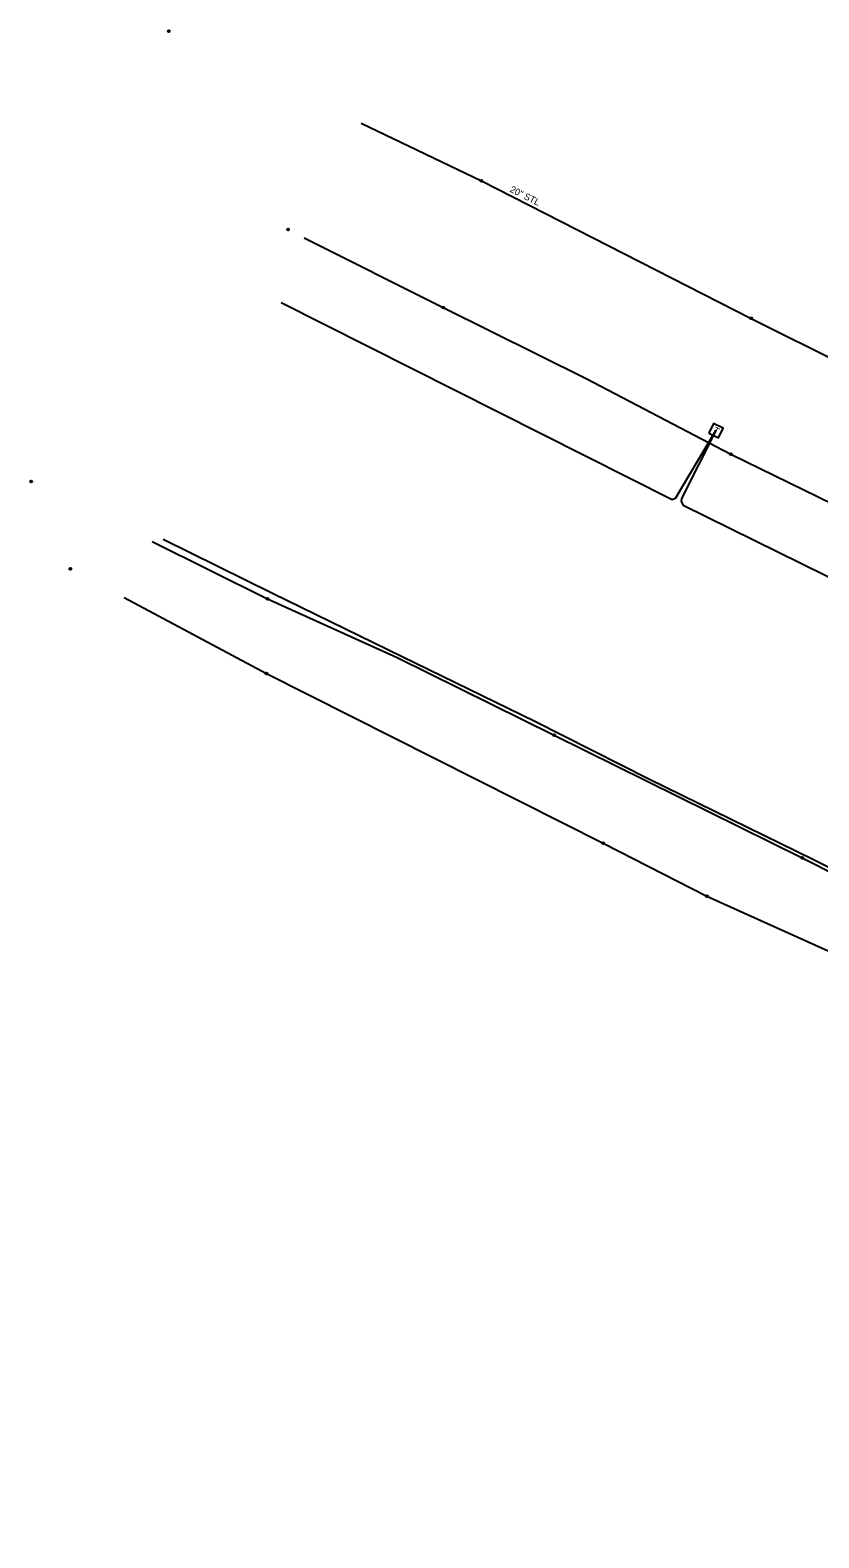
# Model space of a CAD drawing. Extents: x 2244485 to 2250986, y 199568 to 203007.
# Drawn here: x 2244485 to 2244899, y 202217 to 203007 of the extents above; entities that cross this region are included whole.
import ezdxf

# ---------------------------------------------------------------- set-up
doc = ezdxf.new("R2010")
doc.units = 0
for name, color, linetype in [('Default', 7, 'Continuous'), ('Exist Utilities Gas UG Line SUE LOS B', 7, 'Continuous'), ('Exist Utilities Gas UG Line SUE LOS B Text', 7, 'Continuous'), ('Exist Utilities Telephone Pedestal CELL', 7, 'Continuous'), ('Exist Utilities Telephone UG Cable SUE LOS C', 7, 'Continuous'), ('Exist Utilities Telephone UG FO SUE LOS B', 7, 'Continuous'), ('Exist Utilities Telephone UG FO SUE LOS C', 7, 'Continuous')]:
    doc.layers.add(name, color=color, linetype=linetype)

# ---------------------------------------------------------------- blocks, each defined once
blk = doc.blocks.new('SurveyPointCell')
at = {"layer": 'Default'}
for p, q in [((-0.5, 0), (0.5, 0)), ((0, -0.5), (0, 0.5))]:
    blk.add_line(p, q, dxfattribs=at)
blk.add_circle((0, 0), 0.5, dxfattribs=at)

msp = doc.modelspace()

# ---------------------------------------------------------------- linework, layer by layer
at = {"layer": 'Exist Utilities Gas UG Line SUE LOS B'}
msp.add_lwpolyline([(2244658.96, 202958.49), (2244721.96, 202928.3), (2244863.47, 202856.19), (2244912.51, 202831.57), (2245070.07, 202752.33), (2245256.14, 202659.91), (2245331.4, 202622.29), (2245514.38, 202531.76), (2245606.53, 202488.05), (2245652.12, 202465.42), (2245827.69, 202375.08), (2246001.01, 202291.84), (2246162.3, 202211.17), (2246329.12, 202125.74), (2246513.99, 202036.93), (2246642.7, 201974.75), (2246734.96, 201930.33), (2246858.92, 201868.26), (2246999.42, 201799.12), (2247177.53, 201710.71), (2247331.7, 201633.3), (2247466.92, 201567.22), (2247602.4, 201501.88), (2247749.1, 201426.01)], dxfattribs=at)
at = {"layer": 'Exist Utilities Telephone Pedestal CELL'}
msp.add_line((2244844.94, 202797.37), (2244844.94, 202797.37), dxfattribs=at)
msp.add_lwpolyline([(2244841.26, 202796.01), (2244846.3, 202793.58), (2244848.73, 202798.62), (2244843.69, 202801.05), (2244841.26, 202796.01)], dxfattribs=at)
at = {"layer": 'Exist Utilities Telephone UG Cable SUE LOS C'}
msp.add_lwpolyline([(2244616.99, 202864.57), (2244821.95, 202761.17), (2244823.87, 202761.98), (2244826.85, 202767.1), (2244844.94, 202797.37), (2244826.91, 202761.73), (2244826.73, 202760.14), (2244827.76, 202758.24), (2244914.59, 202715.31), (2245013.24, 202666.09), (2245130.24, 202608.24), (2245342.53, 202504.23)], dxfattribs=at)
at = {"layer": 'Exist Utilities Telephone UG FO SUE LOS B'}
for points in [[(2244629.01, 202898.49), (2244702.01, 202861.79), (2244776.88, 202824.58), (2244852.79, 202784.99), (2244944.72, 202739.99), (2245044.68, 202690.62), (2245151.29, 202636.88), (2245260.01, 202583.68), (2245475.72, 202477.57)], [(2244549.31, 202739.15), (2244609.86, 202709.11), (2244677.79, 202678.26), (2244760.05, 202637.59), (2244890.2, 202573.21), (2245003.36, 202516.16), (2245157.86, 202439), (2245297.18, 202369.62), (2245354.5, 202340.75)], [(2244534.64, 202709.84), (2244609.27, 202669.97), (2244785.74, 202581.01), (2244840.19, 202553.14), (2244956.88, 202500.62), (2244986.55, 202486.03), (2245010.04, 202472.71), (2245040, 202457.4), (2245084.78, 202430.15), (2245170.23, 202380.19), (2245207.23, 202360.21), (2245246.97, 202340.05), (2245286.61, 202320.72), (2245320.18, 202303.77), (2245344.49, 202291.92), (2245347.99, 202287.98)]]:
    msp.add_lwpolyline(points, dxfattribs=at)
at = {"layer": 'Exist Utilities Telephone UG FO SUE LOS C'}
msp.add_lwpolyline([(2244555.09, 202740.38), (2244612.45, 202712.07), (2244680.5, 202678.83), (2244750.01, 202644.92), (2244809.78, 202614.66), (2244896.14, 202572.42), (2244969.14, 202536), (2245027.26, 202506.94), (2245218.26, 202412.25), (2245428.66, 202309.78), (2245606.8, 202219.11), (2245703.35, 202173.01), (2245852.59, 202097.7), (2245983.22, 202033.13), (2246107.4, 201971.58), (2246219.73, 201915.39), (2246355.16, 201847.48), (2246395.74, 201823.66), (2246448.95, 201797.92), (2246548.24, 201751.03)], dxfattribs=at)

# ---------------------------------------------------------------- block references
at = {"layer": 'Default'}
for p in [(2244558.14, 203006.82), (2244721.96, 202928.3), (2244620.6, 202902.73), (2244702.01, 202861.79), (2244863.47, 202856.19), (2244852.79, 202784.99), (2244485.92, 202770.6), (2244506.48, 202724.88), (2244609.86, 202709.11), (2244609.27, 202669.97), (2244760.05, 202637.59), (2244785.74, 202581.01), (2244890.2, 202573.21), (2244840.19, 202553.14)]:
    msp.add_blockref('SurveyPointCell', p, dxfattribs=at)

# ---------------------------------------------------------------- texts
at = {"layer": 'Exist Utilities Gas UG Line SUE LOS B Text'}
msp.add_text('20" STL', height=3.5, rotation=333.09153, dxfattribs=at).set_placement((2244736.6, 202922.7))
at = {"layer": 'Exist Utilities Telephone Pedestal CELL'}
msp.add_text('T', height=3.42, rotation=334.29781, dxfattribs=at).set_placement((2244843.18, 202796.32))

doc.saveas('drawing.dxf')
